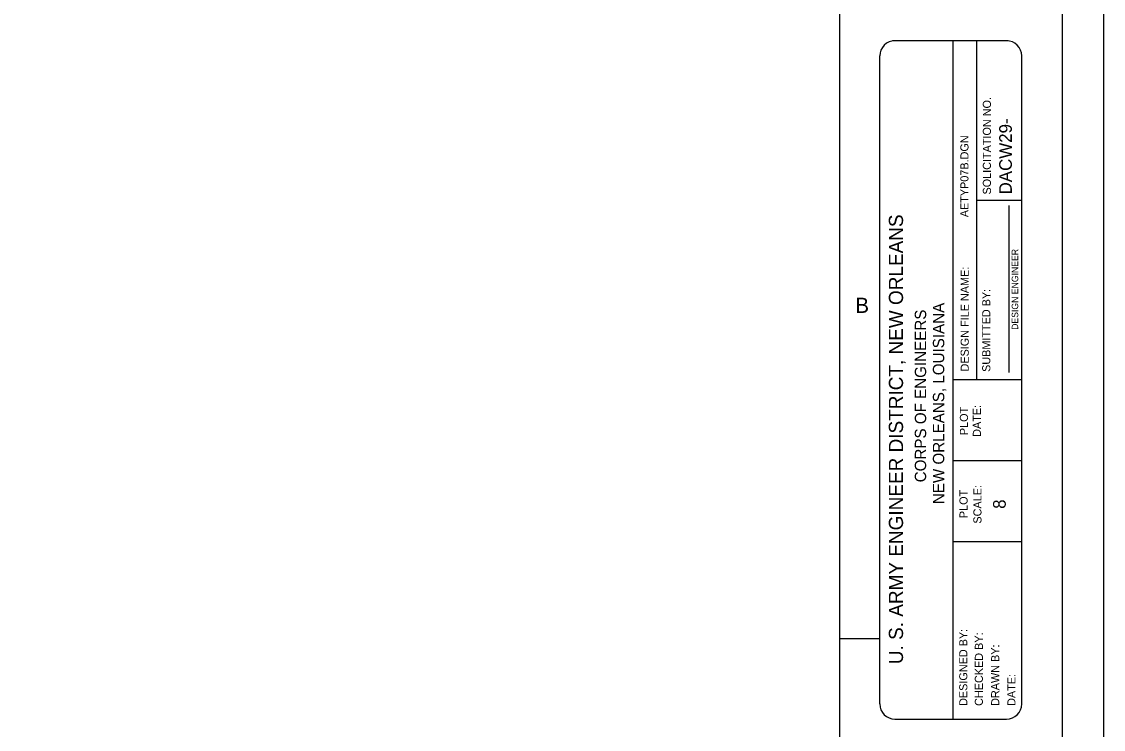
# Model space of a CAD drawing. Extents: x 22388.1 to 22405.7, y 22369.6 to 22390.4.
# Drawn here: x 22398.339 to 22402.79, y 22372.155 to 22375.068 of the extents above; entities that cross this region are included whole.
import ezdxf

# ---------------------------------------------------------------- set-up
doc = ezdxf.new("R2010")
doc.units = 0
for name, color, linetype in [('Level 1', 7, 'Continuous'), ('Level 10', 7, 'Continuous'), ('Level 2', 7, 'Continuous'), ('Level 7', 7, 'Continuous'), ('Level 9', 7, 'Continuous')]:
    doc.layers.add(name, color=color, linetype=linetype)

msp = doc.modelspace()

# ---------------------------------------------------------------- linework, layer by layer
at = {"layer": 'Level 1'}
for p, q in [((22402.3979, 22374.989), (22401.9219, 22374.989)), ((22402.1699, 22374.989), (22402.1699, 22372.197))]:
    msp.add_line(p, q, dxfattribs=at)
msp.add_lwpolyline([(22388.1232, 22380.9477), (22402.7899, 22380.9477), (22402.7899, 22369.6143), (22388.1232, 22369.6143)], close=True, dxfattribs=at)
for points in [[(22402.3914, 22374.989), (22401.9324, 22374.989)], [(22401.8699, 22372.2595), (22401.8699, 22374.9265)], [(22402.4539, 22372.2595), (22402.4539, 22374.9265)], [(22401.9324, 22372.197), (22402.3914, 22372.197)]]:
    msp.add_lwpolyline(points, dxfattribs=at)
for centre, start, end in [((22401.9324, 22374.9265), 90, 180), ((22402.3914, 22374.9265), 0, 90), ((22401.9324, 22372.2595), 180, 270), ((22402.3914, 22372.2595), 270, 0)]:
    msp.add_arc(centre, 0.0625, start, end, dxfattribs=at)
at = {"layer": 'Level 10'}
msp.add_line((22401.7059, 22372.529), (22401.8699, 22372.529), dxfattribs=at)
at = {"layer": 'Level 2'}
for p, q in [((22402.2682, 22374.989), (22402.2682, 22373.593)), ((22402.4539, 22374.3318), (22402.2682, 22374.3318)), ((22402.4019, 22373.6232), (22402.4019, 22374.3103)), ((22402.4539, 22373.593), (22402.1699, 22373.593)), ((22402.4539, 22373.2597), (22402.1699, 22373.2597)), ((22402.4539, 22372.9263), (22402.1699, 22372.9263))]:
    msp.add_line(p, q, dxfattribs=at)
at = {"layer": 'Level 9'}
msp.add_line((22402.6219, 22369.781), (22402.6219, 22380.781), dxfattribs=at)
msp.add_lwpolyline([(22401.7059, 22369.781), (22401.7059, 22380.781)], dxfattribs=at)

# ---------------------------------------------------------------- texts
at = {"layer": 'Level 1'}
for s, height, p in [('SOLICITATION NO.', 0.033336, (22402.3274, 22374.3561)), ('AETYP07B.DGN', 0.033333, (22402.2349, 22374.2627)), ('U. S. ARMY ENGINEER DISTRICT, NEW ORLEANS', 0.058333, (22401.9657, 22372.4235)), ('DESIGN ENGINEER', 0.026664, (22402.4395, 22373.7992)), ('DESIGN FILE NAME:', 0.033336, (22402.236, 22373.6278)), ('SUBMITTED BY:', 0.033336, (22402.3248, 22373.6261)), ('PLOT', 0.03334, (22402.2329, 22373.366)), ('DATE:', 0.03334, (22402.2861, 22373.3591)), ('PLOT', 0.03334, (22402.2312, 22373.0244)), ('SCALE:', 0.03334, (22402.2884, 22373.0017)), ('DESIGNED BY:', 0.033336, (22402.2303, 22372.2516)), ('CHECKED BY:', 0.033336, (22402.2943, 22372.2516)), ('DRAWN BY:', 0.03334, (22402.3616, 22372.2516)), ('DATE:', 0.03334, (22402.4282, 22372.2516))]:
    msp.add_text(s, height=height, rotation=90, dxfattribs=at).set_placement(p)
msp.add_text('B', height=0.0624, dxfattribs=at).set_placement((22401.7699, 22373.869))
at = {"layer": 'Level 7'}
for s, height, p in [('DACW29-', 0.052, (22402.4134, 22374.3565)), ('CORPS OF ENGINEERS', 0.046667, (22402.0608, 22373.1717)), ('NEW ORLEANS, LOUISIANA', 0.046667, (22402.1352, 22373.0818)), ('8', 0.052, (22402.3881, 22373.0625))]:
    msp.add_text(s, height=height, rotation=90, dxfattribs=at).set_placement(p)

doc.saveas('drawing.dxf')
